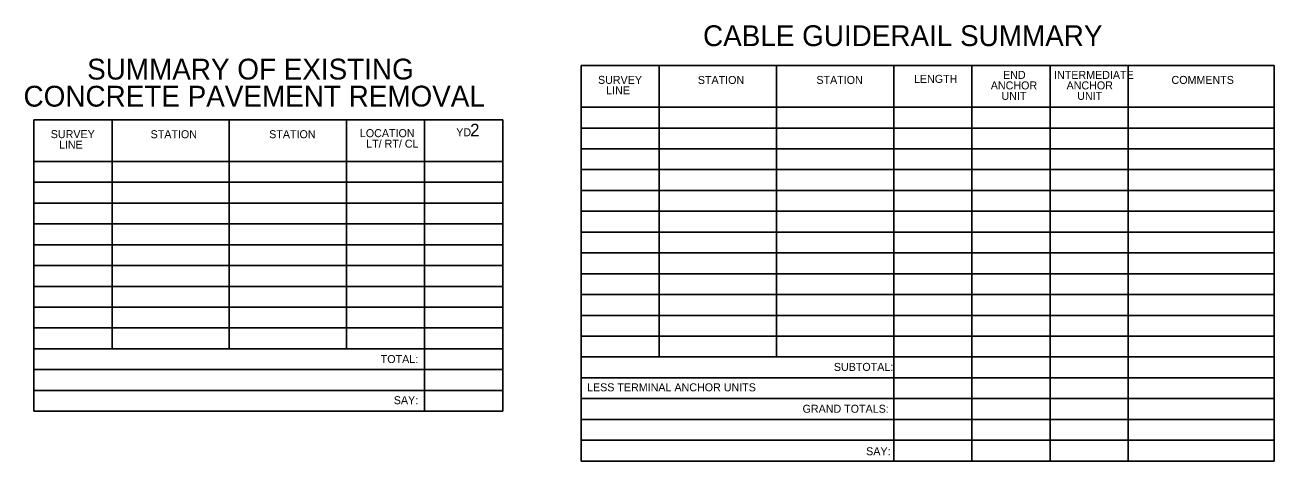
# Model space of a CAD drawing. Extents: x 1318055 to 1318380, y 620349 to 620480.
# Drawn here: x 1318305.2 to 1318380.1, y 620348.6 to 620374.8 of the extents above; entities that cross this region are included whole.
import ezdxf

# ---------------------------------------------------------------- set-up
doc = ezdxf.new("R2010")
doc.units = 0
doc.layers.add('Sheet Summary Combination CELL', color=7, linetype='Continuous')
doc.layers.add('Sheet Summary Combination Grid CELL', color=7, linetype='Continuous')

msp = doc.modelspace()

# ---------------------------------------------------------------- linework, layer by layer
at = {"layer": 'Sheet Summary Combination CELL'}
for p, q in [((1318352.676, 620372.393), (1318352.676, 620372.393)), ((1318353.301, 620372.383), (1318353.301, 620372.383)), ((1318354.206, 620372.403), (1318354.206, 620372.403)), ((1318354.766, 620372.393), (1318354.766, 620372.393)), ((1318319.845, 620369.134), (1318319.845, 620369.134)), ((1318320.47, 620369.124), (1318320.47, 620369.124)), ((1318321.375, 620369.144), (1318321.375, 620369.144)), ((1318321.935, 620369.134), (1318321.935, 620369.134))]:
    msp.add_line(p, q, dxfattribs=at)
at = {"layer": 'Sheet Summary Combination Grid CELL'}
for p, q in [((1318338.551, 620372.398), (1318380.126, 620372.398)), ((1318338.551, 620372.398), (1318338.551, 620348.648)), ((1318343.241, 620372.398), (1318343.241, 620354.898)), ((1318350.276, 620372.398), (1318350.276, 620354.898)), ((1318357.306, 620372.398), (1318357.306, 620348.648)), ((1318361.996, 620372.398), (1318361.996, 620348.648)), ((1318366.686, 620372.398), (1318366.686, 620348.648)), ((1318371.376, 620372.398), (1318371.376, 620348.648)), ((1318380.126, 620372.398), (1318380.126, 620348.648)), ((1318338.551, 620369.898), (1318380.126, 620369.898)), ((1318305.72, 620369.139), (1318333.855, 620369.139)), ((1318305.72, 620369.139), (1318305.72, 620351.639)), ((1318310.41, 620369.139), (1318310.41, 620355.389)), ((1318317.445, 620369.139), (1318317.445, 620355.389)), ((1318324.475, 620369.139), (1318324.475, 620355.389)), ((1318329.165, 620369.139), (1318329.165, 620351.639)), ((1318333.855, 620369.139), (1318333.855, 620351.639)), ((1318338.551, 620368.648), (1318380.126, 620368.648)), ((1318338.551, 620367.398), (1318380.126, 620367.398)), ((1318305.72, 620366.639), (1318333.855, 620366.639)), ((1318338.551, 620366.148), (1318380.126, 620366.148)), ((1318305.72, 620365.389), (1318333.855, 620365.389)), ((1318338.551, 620364.898), (1318380.126, 620364.898)), ((1318305.72, 620364.139), (1318333.855, 620364.139)), ((1318338.551, 620363.648), (1318380.126, 620363.648)), ((1318305.72, 620362.889), (1318333.855, 620362.889)), ((1318338.551, 620362.398), (1318380.126, 620362.398)), ((1318305.72, 620361.639), (1318333.855, 620361.639)), ((1318338.551, 620361.148), (1318380.126, 620361.148)), ((1318305.72, 620360.389), (1318333.855, 620360.389)), ((1318338.551, 620359.898), (1318380.126, 620359.898)), ((1318305.72, 620359.139), (1318333.855, 620359.139)), ((1318338.551, 620358.648), (1318380.126, 620358.648)), ((1318305.72, 620357.889), (1318333.855, 620357.889)), ((1318338.551, 620357.398), (1318380.126, 620357.398)), ((1318305.72, 620356.639), (1318333.855, 620356.639)), ((1318338.551, 620356.148), (1318380.126, 620356.148)), ((1318305.72, 620355.389), (1318333.855, 620355.389)), ((1318338.551, 620354.898), (1318380.126, 620354.898)), ((1318305.72, 620354.139), (1318333.855, 620354.139)), ((1318338.551, 620353.648), (1318380.126, 620353.648)), ((1318305.72, 620352.889), (1318333.855, 620352.889)), ((1318338.551, 620352.398), (1318380.126, 620352.398)), ((1318305.72, 620351.639), (1318333.855, 620351.639)), ((1318338.551, 620351.148), (1318380.126, 620351.148)), ((1318338.551, 620349.898), (1318380.126, 620349.898)), ((1318338.551, 620348.648), (1318380.126, 620348.648))]:
    msp.add_line(p, q, dxfattribs=at)

# ---------------------------------------------------------------- texts
at = {"layer": 'Sheet Summary Combination CELL'}
for s, p in [('CABLE GUIDERAIL SUMMARY', (1318345.87, 620373.565)), ('SUMMARY OF EXISTING', (1318308.916, 620371.558)), ('CONCRETE PAVEMENT REMOVAL', (1318305.101, 620369.933))]:
    msp.add_text(s, height=1.25001, rotation=0.01193, dxfattribs=at).set_placement(p)
for s, p in [('END', (1318363.87, 620371.597)), ('INTERMEDIATE', (1318366.929, 620371.597)), ('SURVEY', (1318339.566, 620371.299)), ('STATION', (1318345.556, 620371.294)), ('STATION', (1318352.67, 620371.296)), ('LENGTH', (1318358.524, 620371.358)), ('ANCHOR', (1318363.133, 620370.967)), ('ANCHOR', (1318367.681, 620370.967)), ('COMMENTS', (1318373.974, 620371.296)), ('LINE', (1318340.057, 620370.669)), ('UNIT', (1318363.773, 620370.337)), ('UNIT', (1318368.32, 620370.337)), ('SURVEY', (1318306.734, 620368.041)), ('STATION', (1318312.725, 620368.035)), ('STATION', (1318319.838, 620368.037)), ('LOCATION', (1318325.28, 620368.099)), ('LINE', (1318307.225, 620367.411)), ('LT/ RT/ CL', (1318325.658, 620367.469)), ('TOTAL:', (1318326.53, 620354.534)), ('SUBTOTAL:', (1318353.718, 620354.061)), ('LESS TERMINAL ANCHOR UNITS', (1318338.909, 620352.836)), ('SAY:', (1318327.314, 620352.063)), ('GRAND TOTALS:', (1318351.841, 620351.548)), ('SAY:', (1318355.655, 620348.995))]:
    msp.add_text(s, height=0.48, dxfattribs=at).set_placement(p)
at = {"layer": 'Sheet Summary Combination Grid CELL'}
for s, height, p in [('YD', 0.48, (1318331.06, 620368.152)), ('2', 0.75, (1318331.897, 620368.152))]:
    msp.add_text(s, height=height, dxfattribs=at).set_placement(p)

doc.saveas('drawing.dxf')
